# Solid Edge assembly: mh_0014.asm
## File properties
Title: grip_l_unit
Author: edge
Template: normal.asm
Last saved by: edge
Revision: 32
Application: Solid Edge
文書内容のタイプ: 1
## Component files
mh_0019.par
mh_0018.par
mh_0017.par
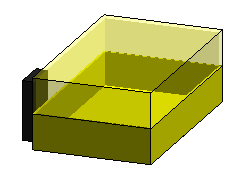
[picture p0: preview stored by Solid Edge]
